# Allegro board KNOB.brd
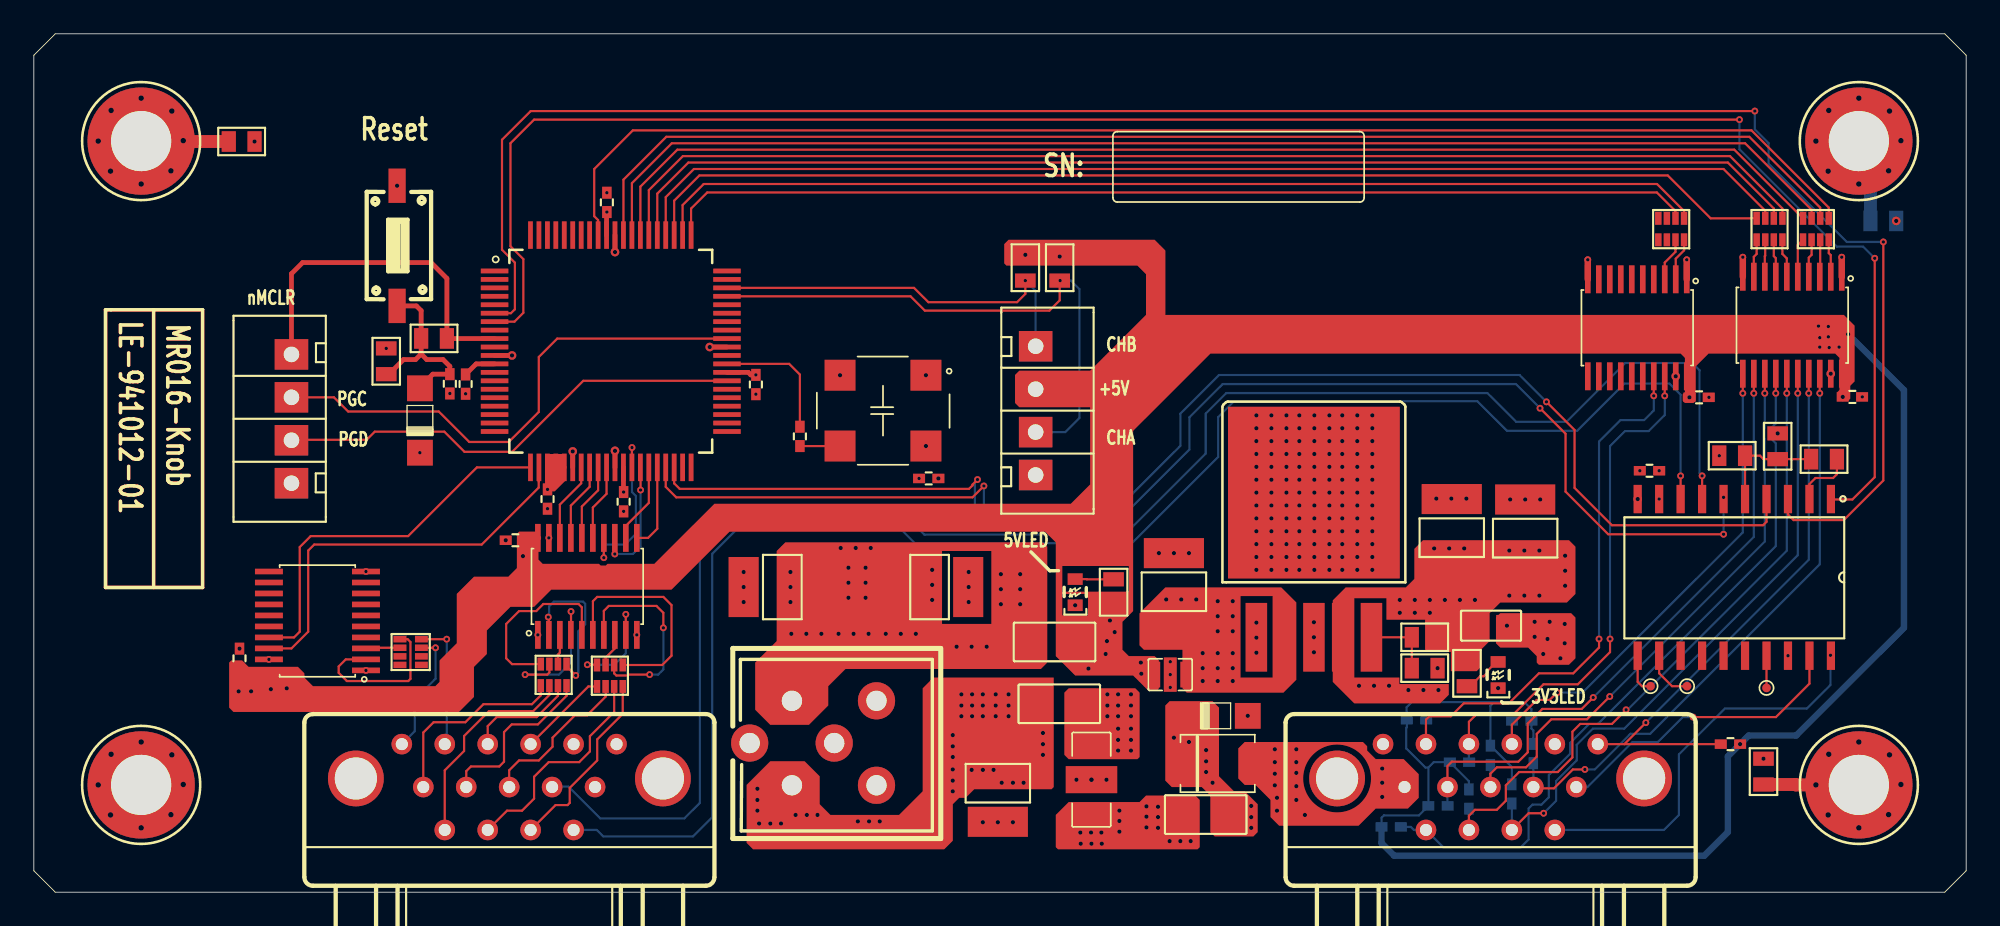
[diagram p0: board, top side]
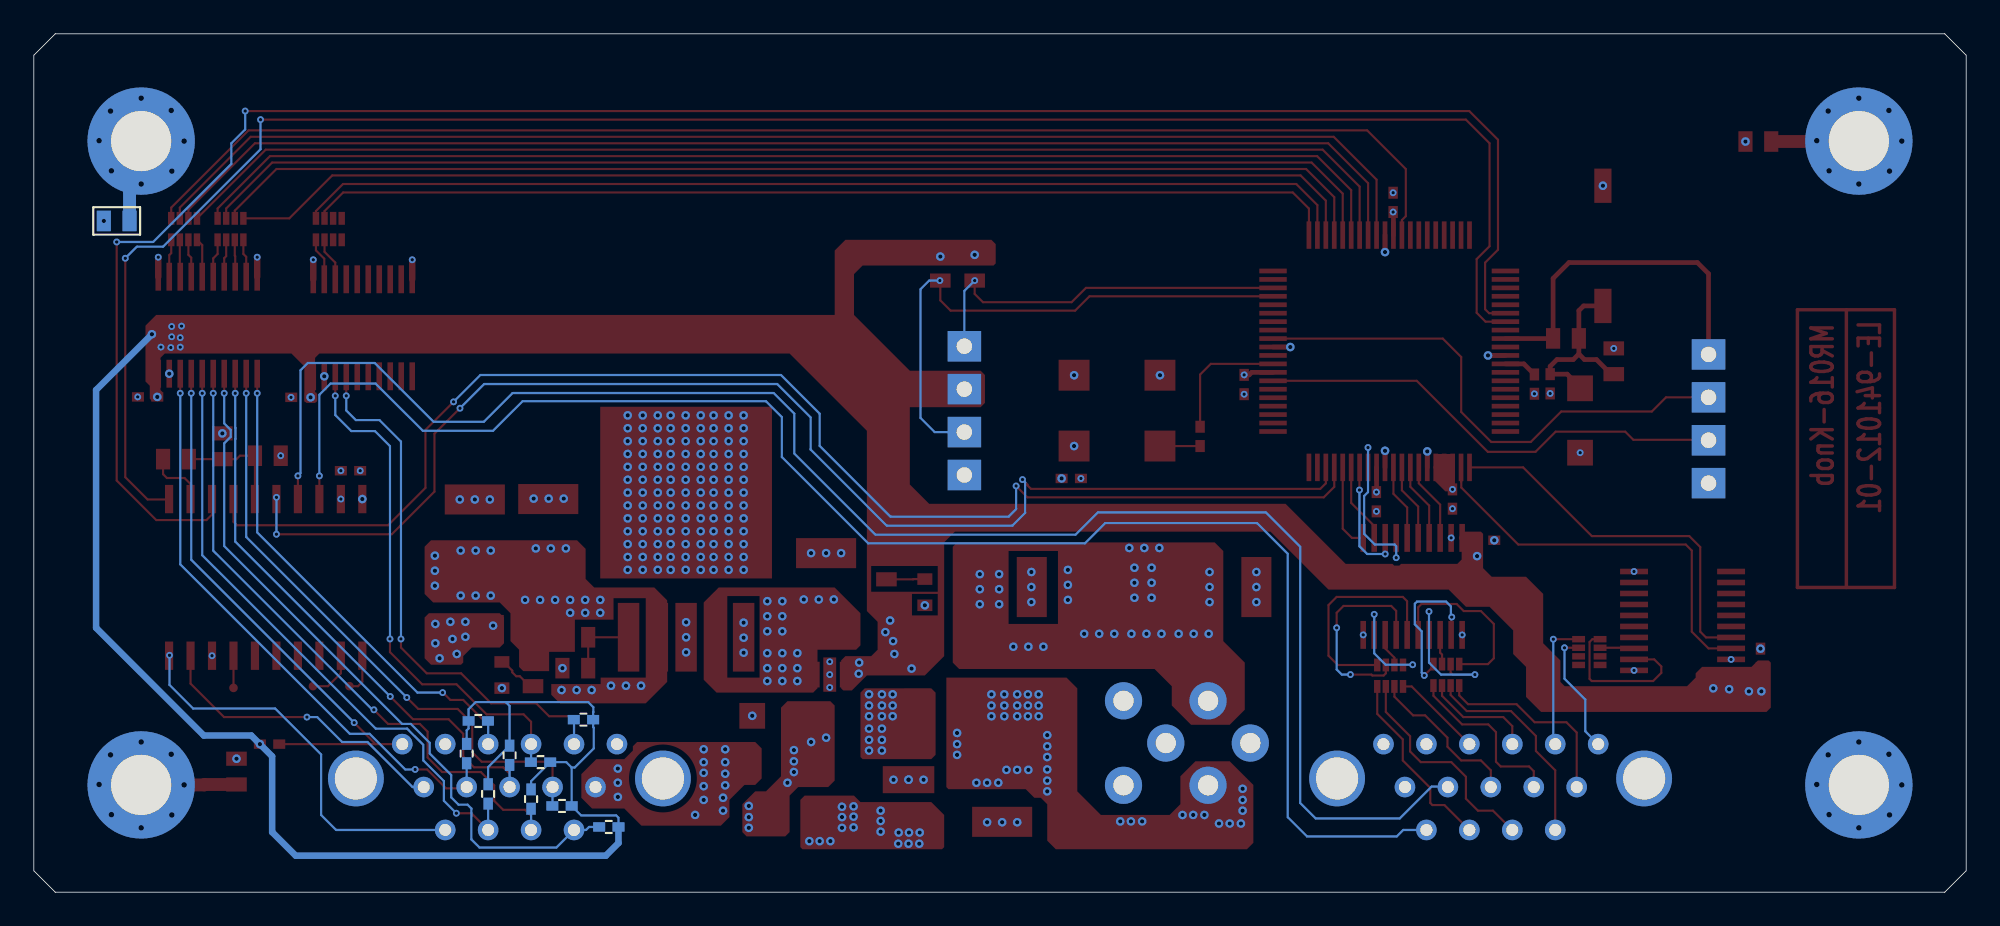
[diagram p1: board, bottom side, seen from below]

Outline 114.3 x 50.8 mm; copper layers: TOP, GND, VCC, BOTTOM. Coordinates in mm from the lower left corner of the outline.
Outline path: 0,49.53 1.27,50.8 113.03,50.8 114.3,49.53 114.3,1.27 113.03,0 1.27,0 0,1.27 0,49.53

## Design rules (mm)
net group N4518649: nets N4518649 N451853317
net group N4559206: nets N4545397 N4559206
net group NMCLR: nets N4540508 NMCLR
net group IO_SIG: nets LAT_LED0 LAT_LED1 LAT_LED2 LAT_LED3 LAT_LED4 LAT_LED5 LAT_LED6 LAT_LED7 LAT_LED8 LAT_LED9 PB0 PB1 PB2 PB3 PB4 PB5 PB6 PB7 PB8 PB9 RX232_DEBUG RX232_PC TX232_DEBUG TX232_PC
net group MECH_PINS: nets N4564556 N4564560 N4564564
net group PRG & ROTARY: nets ICHA ICHB PGC PGD

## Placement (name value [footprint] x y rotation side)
B1  NFM41PC  [FILT1806]  62.56 6.66 90 top
B2  BNX016-01  [BNX1]  42.34 8.83 0 top
B3  NFM21PC  [FILT0805]  67.22 12.88 0 top
C1  0.1uF  [0402]  30.39 23.27 270 top
C2  0.1uF  [0402]  34.89 23.11 270 top
C3  0.1uF  [0402]  33.9 40.82 90 top
C4  0.1uF  [0402]  42.71 30.04 270 top
C5  0.1uF  [0402]  25.54 30.07 270 top
C6  4.7uF  [0402]  24.61 30.09 270 top
C7  0.1uF  [0402]  52.93 24.49 180 top
C8  0.1uF  [0402]  95.57 24.94 180 top
C9  0.1uF  [0402]  28.49 20.83 180 top
C10  0.1uF  [0402]  12.17 13.84 90 top
C11  0.1uF  [0402]  107.57 29.31 0 top
C12  0.1uF  [0402]  98.5 29.29 0 top
C13  47uF  [1812]  57.02 6.45 270 top
C14  47uF  [1812]  44.27 18.06 180 top
C15  47uF  [1812]  52.98 18.06 0 top
C16  47uF  [1812]  67.44 17.78 90 top
C17  47uF  [1812]  83.87 20.98 90 top
C18  47uF  [1812]  88.21 20.95 90 top
C19  10nF 50V  [0603]  102.31 7.14 90 top
C20  10nF 50V  [0603]  109.4 39.73 0 bottom
C21  10nF 50V  [0603]  12.29 44.42 0 top
D1  D1N4148  [LL-34]  22.84 27.91 270 top
D2  PMEG5030  [SOD128]  70.02 7.62 180 top
D3  6V Zener  [LL-34]  69.9 10.44 180 top
D4  Blue LED  [LED0603]  61.59 17.75 270 top
D5  Blue LED  [LED0603]  86.61 12.85 270 top
F1  1A, Slow  [1206]  69.32 4.59 180 top
J1  Programming  [HDR4X1]  15.27 31.83 270 top
J2  ENS1J-B28-L00256L  [HDR4X1]  59.23 24.69 90 top
L1  BLM31PG  [1206]  60.66 11.15 180 top
NOREF  -  []  0 0 90 top
NOREF#2  -  []  6.35 6.35 90 top
NOREF#3  -  []  0 0 0 top
P1  IO CONN  [MIL-DB15]  28.12 6.22 180 top
P2  IO CONN  [MIL-DB15]  86.16 6.22 180 top
R1  10K  [0603]  20.85 31.42 90 top
R2  220  [0603]  23.67 32.77 0 top
R3  49.9 1%  [0402]  45.31 26.97 270 top
R4  NP/0  [0603]  105.89 25.63 0 top
R5  0  [0603]  100.46 25.83 0 top
R6  NP  [0603]  103.15 26.39 90 top
R7  NP/1K  [0603]  60.68 36.96 270 top
R8  NP/1K  [0603]  58.65 36.96 270 top
R9  0  [1206]  60.38 14.81 0 top
R10  680  [0603]  63.87 17.75 90 top
R11  NP/0  [0805]  86.19 15.77 180 top
R12  2K 1%  [0603]  82.27 15.09 0 top
R13  1.2K 1%  [0603]  82.27 13.26 180 top
R14  330  [0603]  84.77 12.95 270 top
R15  1K/2.2K  [0402]  80.29 3.86 180 bottom
R16  1K/2.2K  [0402]  81.79 10.21 180 bottom
R17  1K/2.2K  [0402]  83.06 5.11 180 bottom
R18  1K/2.2K  [0402]  84.33 7.7 180 bottom
R19  1K/2.2K  [0402]  84.89 5.51 90 bottom
R20  1K/2.2K  [0402]  86.16 8.1 90 bottom
R21  1K/2.2K  [0402]  87.43 5.82 90 bottom
R22  1K/2.2K  [0402]  88.01 10.13 0 bottom
R23  1K/2.2K  [0402]  88.7 8.2 90 bottom
R24  1K/2.2K  [0402]  100.36 8.76 0 top
RN1  150  [0402ARRAY]  31.51 13.5 180 top
RN2  150  [0402ARRAY]  34.84 13.45 180 top
RN3  150  [0402ARRAY]  21.66 14.97 270 top
RN4  150  [0402ARRAY]  106.17 39.88 180 top
RN5  150  [0402ARRAY]  103.43 39.88 180 top
RN6  150  [0402ARRAY]  97.61 39.88 180 top
S1  Screw  [HOLE-1]  6.35 6.35 0 top
S2  Screw  [HOLE-1]  107.95 6.35 0 top
S3  Screw  [HOLE-1]  107.95 44.45 0 top
S4  Screw  [HOLE-1]  6.35 44.45 0 top
SW1  uReset  [SMT-SW]  21.49 38.25 270 top
TP1  V+  [STP]  95.63 12.19 0 top
TP2  V+  [STP]  97.79 12.19 0 top
TP3  V-  [STP]  102.49 12.09 0 top
U1  14.7456MHz  [OSC]  50.23 28.5 270 top
U2  PIC18F87J50  [TQFP-80]  34.13 32.01 0 top
U3  MAX3233E  [SO-20]  100.58 18.63 270 top
U4  74HC245  [TSSOP20]  32.74 18.1 90 top
U5  74HC245  [TSSOP20]  16.78 16.05 180 top
U6  74HC245  [TSSOP20]  104.01 33.55 270 top
U7  74HC245  [TSSOP20]  94.84 33.4 270 top
U8  LT1764  [DDPACK]  75.72 15.11 0 top

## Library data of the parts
B1 = NFM18PS: room: PRI_FILT
B2 = BNX016: room: SEC_FILT
B3 = NFM18PS: room: 3V3Reg
C1-C5 = CAP NP: signal model: DEFAULT_CAPACITOR_100000pF_1_2; room: uicro
C6 = CAP NP: signal model: DEFAULT_CAPACITOR_4.7e+06pF_1_2; room: uicro
C7 = CAP NP: signal model: DEFAULT_CAPACITOR_100000pF_1_2; room: uOSC
C8 = CAP NP: signal model: DEFAULT_CAPACITOR_100000pF_1_2; room: RS232
C9 = CAP: signal model: DEFAULT_CAPACITOR_100000pF_1_2; room: oLAT1
C10 = CAP: signal model: DEFAULT_CAPACITOR_100000pF_1_2; room: OLAT2
C11 = CAP: signal model: DEFAULT_CAPACITOR_100000pF_1_2; room: iLAT1
C12 = CAP: signal model: DEFAULT_CAPACITOR_100000pF_1_2; room: iLAT2
C13 = CAP: signal model: DEFAULT_CAPACITOR_4.7e+07pF_1_2; room: PRI_FILT
C14 C15 = CAP: signal model: DEFAULT_CAPACITOR_4.7e+07pF_1_2; room: SEC_FILT
C16-C18 = CAP: signal model: DEFAULT_CAPACITOR_4.7e+07pF_1_2; room: 3V3Reg
C19-C21 = CAP: room: MECH
D1 = 1N4148: room: uicro
D2 = schottky: room: Protection
D3 = FLZ13VB: room: Protection
D4 = LED: room: PW_IN
D5 = LED: room: 3V3Reg
F1 = FUSE: room: Protection
J1 = 4 HEADER
J2 = HEADER 4: room: Rotary
L1 = INDUCTOR FERRITE/SM: signal model: DEFAULT_INDUCTOR_0.001nH_1_2; room: PRI_FILT
P1 = CONNECTOR DB15_1: room: IO CONs
P2 = CONNECTOR DB15_5: room: IO CONs
R1 = res: signal model: DEFAULT_RESISTOR_10000OHM_1_2; room: uicro
R2 = res: signal model: DEFAULT_RESISTOR_220.000000OHM_1_2; room: uicro
R3 = res: signal model: DEFAULT_RESISTOR_0.499OHM_1_2; room: uOSC
R4-R6 = res: signal model: DEFAULT_RESISTOR_0.001OHM_1_2; room: RS232
R7 R8 = res: signal model: DEFAULT_RESISTOR_0.001OHM_1_2; room: Rotary
R9 = res: signal model: DEFAULT_RESISTOR_0.001OHM_1_2; room: PW_IN
R10 = res: signal model: DEFAULT_RESISTOR_680.000000OHM_1_2; room: PW_IN
R11 = res: signal model: DEFAULT_RESISTOR_0.001OHM_1_2; room: 3V3Reg
R12 = res: signal model: DEFAULT_RESISTOR_20.000000OHM_1_2; room: 3V3Reg
R13 = res: signal model: DEFAULT_RESISTOR_12.000000OHM_1_2; room: 3V3Reg
R14 = res: signal model: DEFAULT_RESISTOR_330.000000OHM_1_2; room: 3V3Reg
R15-R24 = res: room: IO CONs
RN1 RN2 = RES Network: room: oLAT1
RN3 = RES Network: room: OLAT2
RN4 RN5 = RES Network: room: iLAT1
RN6 = RES Network: room: iLAT2
S1-S4 = Screw: room: MECH
SW1 = SW PUSHBUTTON: room: uicro
TP1-TP3 = TP: room: RS232
U1 = Oscillator: room: uOSC
U2 = PIC18F87J50: room: uicro
U3 = MAX3233E: room: RS232
U4 = 74HC245/SO: room: oLAT1
U5 = 74HC245/SO: room: OLAT2
U6 = 74HC245/SO: room: iLAT1
U7 = 74HC245/SO: room: iLAT2
U8 = LT1764: room: 3V3Reg

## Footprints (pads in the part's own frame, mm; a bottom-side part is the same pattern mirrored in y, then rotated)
0402
  rect 0.711x0.559 smd: 1(-0.572,0) 2(0.572,0)
0402ARRAY
  rect 0.381x0.762 smd: 1(0,0) 2(0.508,0) 3(1.016,0) 4(1.524,0) 5(1.524,1.27) 6(1.016,1.27) 7(0.508,1.27) 8(0,1.27)
0603
  rect 0.838x1.219 smd: 1(-0.762,0) 2(0.762,0)
0805
  rect 1.27x1.27 smd: 1(-0.94,0) 2(0.94,0)
1206
  rect 1.524x1.778 smd: 1(-1.397,0) 2(1.397,0)
1812
  rect 1.778x3.556 smd: 1(-2.286,0) 2(2.286,0)
BNX1
  round 2.2 hole 1.199: 1(2.499,-2.499) 2(2.499,2.499) 3(7.501,-2.499) 4(0,0) 5(4.999,0) 6(7.501,2.499)
DDPACK
  rect 1.27x4.064 smd: 1(-3.404,-0.025) 2(-1.702,-0.025) 3(0,-0.025) 4(1.702,-0.025) 5(3.404,-0.025)
  rect 10.16x10.16 smd: 6(0,8.534)
FILT0805
  rect 0.508x1.524 smd: 1(-0.851,0) 2(0.851,0)
  rect 0.762x2.032 smd: 3(0,0)
FILT1806
  rect 1.092x1.905 smd: 1(-2.052,0) 2(2.052,0)
  rect 1.6x3.048 smd: 3(0,0)
HDR4X1
  rect 1.803x1.981 hole 0.914: 1(0,-0.025) 2(2.54,-0.025) 3(5.08,-0.025) 4(7.62,-0.025)
HOLE-1
  round 6.35 hole 3.556: 1(0,0)
LED0603
  rect 0.686x0.889 smd: 1(-0.775,0) 2(0.775,0)
LL-34
  rect 1.524x1.524 smd: 1(-1.905,0) 2(1.905,0)
MIL-DB15
  round 1.219 hole 0.711: 1(-5.08,0) 2(-3.81,2.54) 3(-2.54,0) 4(-1.27,2.54) 5(1.27,2.54) 6(2.54,0) 7(3.81,2.54) 8(5.08,0) 9(-6.35,-2.54) 10(-3.81,-2.54) 11(-1.27,-2.54) 12(0,0) 13(1.27,-2.54) 14(3.81,-2.54) 15(6.35,-2.54)
  round 3.302 hole 2.489: 16(-9.093,-0.508) 17(9.068,-0.508)
OSC
  rect 1.829x1.829 smd: 1(-2.095,2.54) 2(-2.095,-2.54) 3(2.095,-2.54) 4(2.095,2.54)
SMT-SW
  rect 2.032x1.016 smd: 1(-3.556,0) 2(3.556,0)
SO-20
  rect 1.676x0.483 smd: 1(-4.636,5.715) 2(-4.636,4.445) 3(-4.636,3.175) 4(-4.636,1.905) 5(-4.636,0.635) 6(-4.636,-0.635) 7(-4.636,-1.905) 8(-4.636,-3.175) 9(-4.636,-4.445) 10(-4.636,-5.715) 11(4.636,-5.715) 12(4.636,-4.445) 13(4.636,-3.175) 14(4.636,-1.905) 15(4.636,-0.635) 16(4.636,0.635) 17(4.636,1.905) 18(4.636,3.175) 19(4.636,4.445) 20(4.636,5.715)
SOD128
  rect 1.199x1.9 smd: 1(-2.2,0) 2(2.2,0)
STP
  round 0.508 smd: 1(0,0)
TQFP-80
  rect 1.626x0.279 smd: 1(-6.873,4.75) 2(-6.873,4.249) 3(-6.873,3.749) 4(-6.873,3.251) 5(-6.873,2.751) 6(-6.873,2.25) 7(-6.873,1.75) 8(-6.873,1.25) 9(-6.873,0.749) 10(-6.873,0.249) 11(-6.873,-0.249) 12(-6.873,-0.749) 13(-6.873,-1.25) 14(-6.873,-1.75) 15(-6.873,-2.25) 16(-6.873,-2.751) 17(-6.873,-3.251) 18(-6.873,-3.749) 19(-6.873,-4.249) 20(-6.873,-4.75) 41(6.873,-4.75) 42(6.873,-4.249) 43(6.873,-3.749) 44(6.873,-3.251) 45(6.873,-2.751) 46(6.873,-2.25) 47(6.873,-1.75) 48(6.873,-1.25) 49(6.873,-0.749) 50(6.873,-0.249) 51(6.873,0.249) 52(6.873,0.749) 53(6.873,1.25) 54(6.873,1.75) 55(6.873,2.25) 56(6.873,2.751) 57(6.873,3.251) 58(6.873,3.749) 59(6.873,4.249) 60(6.873,4.75)
  rect 0.279x1.626 smd: 21(-4.75,-6.873) 22(-4.249,-6.873) 23(-3.749,-6.873) 24(-3.251,-6.873) 25(-2.751,-6.873) 26(-2.25,-6.873) 27(-1.75,-6.873) 28(-1.25,-6.873) 29(-0.749,-6.873) 30(-0.249,-6.873) 31(0.249,-6.873) 32(0.749,-6.873) 33(1.25,-6.873) 34(1.75,-6.873) 35(2.25,-6.873) 36(2.751,-6.873) 37(3.251,-6.873) 38(3.749,-6.873) 39(4.249,-6.873) 40(4.75,-6.873) 61(4.75,6.873) 62(4.249,6.873) 63(3.749,6.873) 64(3.251,6.873) 65(2.751,6.873) 66(2.25,6.873) 67(1.75,6.873) 68(1.25,6.873) 69(0.749,6.873) 70(0.249,6.873) 71(-0.249,6.873) 72(-0.749,6.873) 73(-1.25,6.873) 74(-1.75,6.873) 75(-2.25,6.873) 76(-2.751,6.873) 77(-3.251,6.873) 78(-3.749,6.873) 79(-4.249,6.873) 80(-4.75,6.873)
TSSOP20
  rect 1.651x0.33 smd: 1(-2.87,2.926) 2(-2.87,2.276) 3(-2.87,1.626) 4(-2.87,0.975) 5(-2.87,0.325) 6(-2.87,-0.325) 7(-2.87,-0.975) 8(-2.87,-1.626) 9(-2.87,-2.276) 10(-2.87,-2.926) 11(2.87,-2.926) 12(2.87,-2.276) 13(2.87,-1.626) 14(2.87,-0.975) 15(2.87,-0.325) 16(2.87,0.325) 17(2.87,0.975) 18(2.87,1.626) 19(2.87,2.276) 20(2.87,2.926)

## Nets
3V3: C1.1 C2.1 C3.1 C4.1 C7.1 C8.1 D1.2 R1.2 R5.1 R11.1 U1.1(EN/TRI) U1.4(VCC) U2.23(VUSB) U2.24(ENVREG) U2.25(AVDD) U2.32(VDD) U2.48(VDD_1) U2.71(VDD_2) U3.9(VCC) U3.10(F\O\R\C\E\O\F\F\)
5V: B3.1(IO1) C9.1 C10.1 C11.1 C12.1 J2.3 R7.1 R8.1 R9.2 R10.1 R15.2 R16.2 R17.2 R18.2 R19.2 R20.2 R21.2 R22.2 R23.2 R24.2 U4.20(VCC) U5.20(VCC) U6.20(VCC) U7.20(VCC)
5V_FILT: B2.2(CB) C14.1 C15.1 R9.1
5VI: B2.1(B) C13.1 L1.2
CGND: B1.3(G) B2.3(PSG) C13.2 D3.1(A) P2.15 P2.17(GND#17)
DG: B2.4(CG#4) B2.5(CG#5) B2.6(CG#6) B3.3(G) C1.2 C2.2 C3.2 C4.2 C5.2 C6.2 C7.2 C8.2 C9.2 C10.2 C11.2 C12.2 C14.2 C15.2 C16.2 C17.2 C18.2 C19.2 C20.2 C21.2 D4.2(CATHODE) D5.2(CATHODE) J1.4 J2.1 P1.1 P1.9 P1.10 P1.16(GND#16) P1.17(GND#17) P2.10 P2.16(GND#16) R6.2 R13.1 S1.1(H) SW1.1 U1.2(GND) U2.11(VSS) U2.26(AVSS) U2.31(VSS_1) U2.51(VSS_2) U2.70(VSS_3) U3.18(GND) U4.1(DIR) U4.10(GND) U4.19(O\E\) U5.1(DIR) U5.10(GND) U5.19(O\E\) U6.1(DIR) U6.10(GND) U6.19(O\E\) U7.1(DIR) U7.10(GND) U7.19(O\E\) U8.1(S\H\D\N\) U8.3(GND#3) U8.6(GND#6)
ICHA: J2.2 R7.2 U2.57(RB1/INT1/PMA4)
ICHB: J2.4 R8.2 U2.58(RB0/FLT0/INT0)
ILAT_PB0: RN4.1 U2.72(RD0/AD0/PMD0)
ILAT_PB1: RN4.2 U2.69(RD1/AD1/PMD1)
ILAT_PB2: RN4.3 U2.68(RD2/AD2/PMD2)
ILAT_PB3: RN4.4 U2.67(RD3/AD3/PMD3)
ILAT_PB4: RN5.1 U2.66(RD4/AD4/PMD4/SDO2)
ILAT_PB5: RN5.2 U2.65(RD5/AD5/PMD5/SDI2/SDA2)
ILAT_PB6: RN5.3 U2.64(RD6/AD6/PMD6/SCK2/SCL2)
ILAT_PB7: RN5.4 U2.63(RD7/AD7/PMD7/S\S\2\)
ILAT_PB8: RN6.1 U2.62(RJ0/ALE)
ILAT_PB9: RN6.2 U2.61(RJ1/O\E\)
IRX1: U2.38(RC7/RX1/DT1) U3.6(R1OUT)
IRX2: U2.7(RG2/PMA6/RX2/DT2) U3.1(R2OUT)
LAT_LED0: P1.6 RN1.8
LAT_LED1: P1.13 RN1.7
LAT_LED2: P1.7 RN1.6
LAT_LED3: P1.8 RN1.5
LAT_LED4: P1.4 RN2.8
LAT_LED5: P1.5 RN2.7
LAT_LED6: P1.12 RN2.6
LAT_LED7: P1.11 RN2.5
LAT_LED8: P1.14 RN3.8
LAT_LED9: P1.15 RN3.7
NMCLR: J1.1 R2.2 U2.9(\M\C\L\R\)
OLED0: U2.27(RA3/AN3/VREF+) U4.18(B0)
OLED1: U2.28(RA2/AN2/VREF-) U4.17(B1)
OLED2: U2.29(RA1/AN1) U4.16(B2)
OLED3: U2.30(RA0/AN0) U4.15(B3)
OLED4: U2.33(RA5/PMD4/AN4/C2INA) U4.14(B4)
OLED5: U2.34(RA4/PMD5/T0CKI) U4.13(B5)
OLED6: U2.35(RC1/T1OSI/ECCP2/P2A) U4.12(B6)
OLED7: U2.36(RC0/T1OSO/T13CKI) U4.11(B7)
OLED8: U2.22(RH4/PMD3/AN12/P3C/C2INC) U5.18(B0)
OLED9: U2.21(RH5/PMBE/AN13/P3B/C2IND) U5.17(B1)
OTX1: U2.37(RC6/TX1/CK1) U3.4(T1IN)
OTX2: U2.6(RG1/PMA7/TX2/CK2) U3.3(T2IN)
PB0: P2.3 R23.1 U6.18(B0)
PB1: P2.9 R24.1 U6.17(B1)
PB2: P2.4 R21.1 U6.16(B2)
PB3: P2.5 R19.1 U6.15(B3)
PB4: P2.7 R15.1 U6.14(B4)
PB5: P2.12 R20.1 U6.13(B5)
PB6: P2.6 R17.1 U6.12(B6)
PB7: P2.11 R22.1 U6.11(B7)
PB8: P2.13 R18.1 U7.18(B0)
PB9: P2.14 R16.1 U7.17(B1)
PGC: J1.2 U2.52(RB6/KBI2/PGC)
PGD: J1.3 U2.47(RB7/KBI3/PGD)
PRE3V: C17.1 C18.1 R11.2 R12.2 R14.1 U8.4(OUT)
PW_IN: D2.1(A) P2.8
PWI1: D2.2(K) D3.2(K) F1.1
PWI2: B1.1(IO1) F1.2
PWI3: B1.2(IO2) L1.1
REG_IN: B3.2(IO2) C16.1 U8.2(IN)
RX232_DEBUG: P2.1 U3.19(T2OUT)
RX232_PC: P1.3 U3.7(T1OUT)
TX232_DEBUG: P2.2 U3.20(R2IN)
TX232_PC: P1.2 U3.8(R1IN)
N4516923: R12.1 R13.2 U8.5(ADJ)
N4518449: TP1.1 U3.11(V +)
N4518453: TP2.1 U3.12(V+)
N4518457: TP3.1 U3.17(V-)
N4518649: R4.1 R5.2 R6.1 U3.5(FORCEON)
N4527797: RN4.8 U6.2(A0)
N4527803: RN5.7 U6.7(A5)
N4527809: RN4.7 U6.3(A1)
N4527815: RN5.5 U6.9(A7)
N4527821: RN4.5 U6.5(A3)
N4527827: RN5.8 U6.6(A4)
N4527833: RN5.6 U6.8(A6)
N4527839: RN4.6 U6.4(A2)
N4527957: RN6.7 U7.3(A1)
N4527963: RN6.8 U7.2(A0)
N4530864: D5.1(ANODE) R14.2
N4530991: D4.1(ANODE) R10.2
N4540508: C6.1 D1.1 R1.1 R2.1 SW1.2
N4541200: C5.1 U2.12(VDDCORE/VCAP)
N4545397: R3.2 U1.3(CKO)
N4559206: R3.1 U2.49(OSC1/CLKI/RA7)
N4562922: RN3.2 U5.3(A1)
N4562926: RN3.1 U5.2(A0)
N4563314: RN2.1 U4.6(A4)
N4563346: RN2.2 U4.7(A5)
N4563350: RN2.3 U4.8(A6)
N4563354: RN2.4 U4.9(A7)
N4563358: RN1.4 U4.5(A3)
N4563362: RN1.3 U4.4(A2)
N4563366: RN1.2 U4.3(A1)
N4563370: RN1.1 U4.2(A0)
N4564556: C21.1 S4.1(H)
N4564560: C20.1 S3.1(H)
N4564564: C19.1 S2.1(H)
N451853317: R4.2 U3.2(I\N\V\A\L\I\D\)

Pads without a net: RN3 3 4 5 6; RN6 3 4 5 6; U2 1 2 3 4 5 8 10 13 14 15 16 17 18 19 20 39 40 41 42 43 44 45 46 50 53 54 55 56 59 60 73 74 75 76 77 78 79 80; U3 13 14 15 16; U5 4 5 6 7 8 9 11 12 13 14 15 16; U7 4 5 6 7 8 9 11 12 13 14 15 16

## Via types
v1: diameter 0.406, hole 0.203, TOP to BOTTOM, 89 vias
v2: diameter 0.508, hole 0.254, TOP to BOTTOM, 372 vias
v3: diameter 0.61, hole 0.33, TOP to BOTTOM, 32 vias

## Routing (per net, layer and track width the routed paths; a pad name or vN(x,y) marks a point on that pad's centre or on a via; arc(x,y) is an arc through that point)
3V3: length 6.9
  TOP w0.279: U2.48 42.26,30.76 42.41,30.61 v1(42.71,30.61) ; U2.25 U2.24 U2.23 30.39,25.13 v1(30.39,23.84) ; v1(34.89,23.68) 34.88,23.69 U2.32 ; U2.71 33.88,40.23 v1(33.9,40.25)
  vias: v1(20.85,32.18) v1(22.83,26.01) v1(96.14,24.94) v1(96.14,23.27) v1(99.69,25.83) v2(52.77,30.59) v2(52.77,26.4) v2(53.51,24.49) v2(87.13,15.77) v2(88.77,16) v2(88.77,15.11) v2(89.28,14.1) v2(89.53,14.99) v2(89.66,16) v2(90.3,13.84) v2(90.55,15.88) v2(90.55,14.73) v2(94.87,23.27)
5V: length 88.8
  TOP w0.381: U4.20 29.67,20.83 C9.1
  BOTTOM w0.127: 86.39,11.25 81.51,11.25 81.2,10.95 81.2,10.67 81.22,10.66 R16.2 81.22,9.77 81.18,9.73 81.18,8.51 82.31,7.38 82.49,7.38 ; 86.39,11.25 86.16,11.02 R20.2 87.43,7.4 R21.2 ; 86.39,11.25 88.16,11.25 88.58,10.83 R22.2 88.58,9.69 88.7,9.58 R23.2 ; 82.49,7.38 R17.2 81.93,4.55 79.86,4.55 79.72,4.41 R15.2 ; 82.49,7.38 82.8,7.7 R18.2 84.89,6.57 R19.2
  BOTTOM w0.381: R15.2 79.72,2.91 80.47,2.16 98.81,2.16 100.2,3.56 100.2,8.04 v2(100.93,8.76) 101.43,9.27 104.24,9.27 110.62,15.65 110.62,29.72 v2(107.31,33.02)
  vias: v1(105.56,33.5) v1(105.64,32.82) v1(105.64,32.26) v1(106.15,33.48) v1(106.15,32.87) v1(106.2,32.23) v1(106.78,32.26) v2(12.12,11.89) v2(12.85,11.89) v2(14.02,12.01) v2(14.96,12.06) v2(28.93,19.89) v2(58.65,37.72) v2(60.68,37.62) v2(62.38,13.23) v2(63.4,14.1) v2(63.47,14.86) v2(63.65,16.08) v2(63.93,15.39) v2(65.48,13.59) v2(65.51,12.93) v2(97.93,29.29) v2(107,29.31)
5V_FILT:
  vias: v2(44.75,18.95) v2(44.75,18.06) v2(44.75,17.17) v2(44.81,15.29) v2(45.69,15.29) v2(46.58,15.29) v2(47.6,15.29) v2(47.73,20.37) v2(48.18,19.2) v2(48.18,18.31) v2(48.18,17.42) v2(48.49,15.29) v2(48.62,20.37) v2(49.2,19.2) v2(49.2,18.31) v2(49.2,17.42) v2(49.38,15.29) v2(49.5,20.37) v2(50.39,15.29) v2(51.28,15.29) v2(52.17,15.29) v2(53.14,19.08) v2(53.14,18.19) v2(53.14,17.3) v2(54.58,14.53) v2(55.47,14.53) v2(56.36,14.53) v2(57.2,18.82) v2(57.2,17.93) v2(57.2,17.04) v2(58.34,18.82) v2(58.34,17.93) v2(58.34,17.04)
5VI:
  vias: v2(42.8,6.12) v2(42.8,5.46) v2(42.8,4.83) v2(42.9,4.06) v2(43.56,4.06) v2(44.2,4.06) v2(45.06,4.57) v2(45.72,4.57) v2(46.35,4.57) v2(48.74,4.19) v2(49.41,4.19) v2(50.04,4.19) v2(54.36,9.3) v2(54.36,8.63) v2(54.36,8) v2(54.36,7.26) v2(54.36,6.6) v2(54.36,5.97) v2(54.86,11.71) v2(54.86,11.05) v2(54.86,10.41) v2(55.5,11.71) v2(55.5,11.05) v2(55.5,10.41) v2(55.47,7.24) v2(56.13,11.71) v2(56.13,11.05) v2(56.13,10.41) v2(56.14,7.24) v2(56.77,7.24) v2(56.9,11.71) v2(56.9,11.05) v2(56.9,10.41) v2(57.25,6.48) v2(57.66,11.71) v2(57.66,11.05) v2(57.66,10.41) v2(57.91,6.48) v2(58.55,6.48) v2(59.69,9.42) v2(59.69,8.76) v2(59.69,8.13)
CGND:
  vias: v2(56.13,4.14) v2(57.02,4.14) v2(57.91,4.14) v2(61.67,6.65) v2(62.56,6.66) v2(62.56,6.65) v2(63.45,6.65) v2(71.81,10.44)
DG: length 9.6
  TOP w0.279: U2.70 v2(34.38,37.88) ; U2.26 v2(31.88,26.09) ; U2.31 v2(34.38,26.12) ; U2.51 v2(39.98,32.26) ; U2.11 v2(28.29,31.77)
  TOP w0.381: U6.1 v1(106.94,37.58) ; U7.10 v1(91.92,37.43) ; U7.1 v1(97.77,37.43) ; U6.10 v1(101.09,37.58)
  vias: v1(13.91,13.78) v1(19.65,18.98) v1(19.65,13.13) v1(24.61,29.51) v1(25.54,29.5) v1(29.81,15.23) v1(30.39,22.69) v1(30.46,20.97) v1(33.9,41.39) v1(34.89,22.54) v1(35.67,15.23) v1(42.71,29.47) v1(52.36,24.49) v1(67.22,13.64) v1(67.22,12.88) v1(67.22,12.12) v1(95,24.94) v1(99.09,29.29) v1(103.76,14) v1(108.15,29.31) v2(12.17,14.41) v2(13.06,44.42) v2(21.49,41.81) v2(27.91,20.83) v2(41.99,18.95) v2(41.99,18.06) v2(41.99,17.17) v2(47.69,30.59) v2(55.3,18.95) v2(55.3,18.06) v2(55.3,17.17) v2(61.59,16.98) v2(66.55,20.07) v2(67.44,20.07) v2(68.33,20.07) v2(72.31,28.22) v2(72.31,27.46) v2(72.31,26.7) v2(72.31,25.93) v2(72.31,25.17) v2(72.31,24.41) v2(72.31,23.65) v2(72.31,22.89) v2(72.31,22.12) v2(72.31,21.36) v2(72.31,20.6) v2(72.31,19.84) v2(72.31,19.08) v2(72.31,15.95) v2(72.31,15.06) v2(72.31,14.17) v2(73.2,28.22) v2(73.2,27.46) v2(73.2,26.7) v2(73.2,25.93) v2(73.2,25.17) v2(73.2,24.41) v2(73.2,23.65) v2(73.2,22.89) v2(73.2,22.12) v2(73.2,21.36) v2(73.2,20.6) v2(73.2,19.84) v2(73.2,19.08) v2(74.09,28.22) v2(74.09,27.46) v2(74.09,26.7) v2(74.09,25.93) v2(74.09,25.17) v2(74.09,24.41) v2(74.09,23.65) v2(74.09,22.89) v2(74.09,22.12) v2(74.09,21.36) v2(74.09,20.6) v2(74.09,19.84) v2(74.09,19.08) v2(74.85,28.22) v2(74.85,27.46) v2(74.85,26.7) v2(74.85,25.93) v2(74.85,25.17) v2(74.85,24.41) v2(74.85,23.65) v2(74.85,22.89) v2(74.85,22.12) v2(74.85,21.36) v2(74.85,20.6) v2(74.85,19.84) v2(74.85,19.08) v2(75.74,28.22) v2(75.74,27.46) v2(75.74,26.7) v2(75.74,25.93) v2(75.74,25.17) v2(75.74,24.41) v2(75.74,23.65) v2(75.74,22.89) v2(75.74,22.12) v2(75.74,21.36) v2(75.74,20.6) v2(75.74,19.84) v2(75.74,19.08) v2(75.72,15.98) v2(75.72,15.09) v2(75.72,14.2) v2(76.63,28.22) v2(76.63,27.46) v2(76.63,26.7) v2(76.63,25.93) v2(76.63,25.17) v2(76.63,24.41) v2(76.63,23.65) v2(76.63,22.89) v2(76.63,22.12) v2(76.63,21.36) v2(76.63,20.6) v2(76.63,19.84) v2(76.63,19.08) v2(77.39,28.22) v2(77.39,27.46) v2(77.39,26.7) v2(77.39,25.93) v2(77.39,25.17) v2(77.39,24.41) v2(77.39,23.65) v2(77.39,22.89) v2(77.39,22.12) v2(77.39,21.36) v2(77.39,20.6) v2(77.39,19.84) v2(77.39,19.08) v2(78.28,28.22) v2(78.28,27.46) v2(78.28,26.7) v2(78.28,25.93) v2(78.28,25.17) v2(78.28,24.41) v2(78.28,23.65) v2(78.28,22.89) v2(78.28,22.12) v2(78.28,21.36) v2(78.28,20.6) v2(78.28,19.84) v2(78.28,19.08) v2(79.17,28.22) v2(79.17,27.46) v2(79.17,26.7) v2(79.17,25.93) v2(79.17,25.17) v2(79.17,24.41) v2(79.17,23.65) v2(79.17,22.89) v2(79.17,22.12) v2(79.17,21.36) v2(79.17,20.6) v2(79.17,19.84) v2(79.17,19.08) v2(82.96,23.29) v2(83.03,13.26) v2(83.85,23.29) v2(84.73,23.29) v2(86.61,12.08) v2(87.33,23.24) v2(88.21,23.24) v2(89.1,23.24) v2(97.12,30.53) v2(102.31,7.9) v2(103.15,27.15) v2(106.29,30.68) v2(110.16,39.73) v3(3.81,6.35) v3(4.54,4.57) v3(4.57,8.16) v3(6.35,8.89) v3(6.35,3.81) v3(8.11,4.59) v3(8.16,8.13) v3(8.84,6.38)
ICHA: length 33.4
  TOP w0.127: R7.2 60.68,35.03 60.07,34.42 52.7,34.42 51.86,35.27 U2.57
  BOTTOM w0.127: J2.2 61.01,27.23 61.85,28.07 61.85,35.69 61.34,36.2 v1(60.71,36.2)
ICHB: length 23.1
  TOP w0.127: U2.58 52.06,35.76 52.91,34.92 58.16,34.92 58.65,35.41 v1(58.65,36.2)
  BOTTOM w0.127: v1(58.65,36.2) 59.26,35.59 J2.4
ILAT_PB0: length 80.5
  TOP w0.127: U2.72 33.38,39.77 33.15,40.01 33.15,42.8 35.43,45.09 101.6,45.09 106.17,40.51 RN4.1
ILAT_PB1: length 77.5
  TOP w0.127: U2.69 34.88,42.17 37.41,44.7 101.47,44.7 105.66,40.51 RN4.2
ILAT_PB2: length 76
  TOP w0.127: U2.68 35.38,41.96 37.74,44.32 101.22,44.32 105.16,40.39 RN4.3
ILAT_PB3: length 74.2
  TOP w0.127: U2.67 35.88,41.76 38.06,43.94 100.58,43.94 RN4.4
ILAT_PB4: length 72.4
  TOP w0.127: RN5.1 103.43,40.46 100.33,43.56 38.39,43.56 36.38,41.55 U2.66
ILAT_PB5: length 71
  TOP w0.127: U2.65 36.88,41.34 38.72,43.18 100.2,43.18 102.92,40.46 RN5.2
ILAT_PB6: length 69.4
  TOP w0.127: U2.64 37.38,41.13 39.04,42.8 99.95,42.8 102.41,40.33 RN5.3
ILAT_PB7: length 67.7
  TOP w0.127: RN5.4 99.19,39.88 96.65,42.42 39.37,42.42 37.88,40.92 U2.63
ILAT_PB8: length 62.6
  TOP w0.127: RN6.1 97.61,40.31 96.01,41.91 39.62,41.91 38.38,40.66 U2.62
ILAT_PB9: length 61.1
  TOP w0.127: RN6.2 97.1,40.31 96,41.41 39.83,41.41 38.88,40.46 U2.61
IRX1: length 78.4
  TOP w0.127: v1(99.95,21.18) 93.12,21.18 90.6,23.71 90.6,27.13 v1(89.09,28.64) ; v1(55.82,24.42) 55.52,24.12 55.52,24.07 55.32,23.87 38.21,23.87 37.88,24.2 U2.38
  BOTTOM w0.127: v1(99.95,21.18) v1(99.95,23.37) ; v1(55.82,24.42) 55.66,24.26 55.66,22.45 56.42,21.69 63.85,21.69 68.35,26.2 68.35,28.1 70.32,30.07 87.66,30.07 v1(89.09,28.64)
IRX2: length 114.1
  TOP w0.127: v1(100.89,45.72) 29.59,45.72 28.19,44.32 28.19,38.23 28.96,37.47 28.96,34.29 28.43,33.76 U2.7 ; U3.1 106.32,23.24 107.57,23.24 108.89,24.56 v1(108.89,37.52)
  BOTTOM w0.127: v1(100.89,45.72) 100.89,43.97 106.65,38.2 108.2,38.2 v1(108.89,37.52)
LAT_LED0: length 10.4
  TOP w0.127: RN1.8 31.51,11.62 29.82,9.93 28.27,9.93 27.81,9.47 27.81,7.72 27.53,7.44 25.86,7.44 25.58,7.16 P1.6
LAT_LED1: length 6.6
  TOP w0.127: P1.13 26.85,9.83 27.38,10.36 29.74,10.36 31,11.62 RN1.7
LAT_LED2: length 12.6
  TOP w0.127: RN1.6 30.5,11.67 29.54,10.72 26.92,10.72 25.45,9.25 25.45,8.36 24.31,7.21 P1.7
LAT_LED3: length 11.7
  TOP w0.127: P1.8 23.04,9.45 23.65,10.06 25.53,10.06 26.59,11.13 29.46,11.13 29.99,11.65 RN1.5
LAT_LED4: length 11.2
  TOP w0.127: P1.4 30.86,5.16 31.57,5.16 31.7,5.28 31.7,6.17 33.32,7.8 33.32,9.04 34.84,10.55 RN2.8
LAT_LED5: length 13.2
  TOP w0.127: P1.5 27.99,4.83 28.88,4.83 29.59,5.54 29.59,6.83 30.45,7.7 32.26,7.7 32.89,8.33 32.89,9.23 34.33,10.67 RN2.7
LAT_LED6: length 9.4
  TOP w0.127: RN2.6 33.82,11.57 32.72,10.46 32,10.46 30.68,9.14 30.68,8.61 29.87,7.8 28.7,7.8 28.12,7.21 P1.12
LAT_LED7: length 5.3
  TOP w0.127: P1.11 32.8,12.18 RN2.5
LAT_LED8: length 7.8
  TOP w0.127: RN3.8 v1(24.42,14.97)
  BOTTOM w0.127: v1(24.42,14.97) 24.42,8.88 P1.14
LAT_LED9: length 7.4
  TOP w0.127: RN3.7 v1(23.76,14.47)
  BOTTOM w0.127: P1.15 22.53,9.53 22.53,11.4 23.76,12.64 v1(23.76,14.47)
NMCLR: length 21
  TOP w0.279: J1.1 15.24,36.6 15.9,37.26 23.5,37.26 24.43,36.32 R2.2 24.44,32.76 U2.9
OLED0: length 4.7
  TOP w0.127: U4.18 31.11,22.94 32.38,24.2 U2.27
OLED1: length 4.6
  TOP w0.127: U2.28 32.88,23.99 31.77,22.88 U4.17
OLED2: length 4.6
  TOP w0.127: U2.29 33.38,23.78 32.42,22.82 U4.16
OLED3: length 4.5
  TOP w0.127: U4.15 33.07,22.77 33.88,23.58 U2.30
OLED4: length 10.4
  TOP w0.127: U2.33 35.38,26.31 v1(35.38,26.31) ; U4.14 v1(33.72,19.8)
  BOTTOM w0.127: v1(33.72,19.8) 33.72,20.48 33.81,20.57 34.98,20.57 35.61,21.21 35.61,23.45 35.38,23.68 v1(35.38,26.31)
OLED5: length 7.3
  TOP w0.127: v1(35.89,23.8) 35.89,25.13 U2.34 ; U4.13 v1(34.37,20.02)
  BOTTOM w0.127: v1(34.37,20.02) 35.43,20.02 35.89,20.47 v1(35.89,23.8)
OLED6: length 4.7
  TOP w0.127: U4.12 35.02,21.68 36.38,23.04 U2.35
OLED7: length 5.1
  TOP w0.127: U2.36 36.88,21.51 36.33,20.97 U4.11
OLED8: length 23.9
  TOP w0.127: U5.18 15.24,14.43 16.23,15.42 16.23,20.22 16.59,20.57 26.49,20.57 29.87,23.95 29.87,24.29 29.88,24.31 U2.22
OLED9: length 22.6
  TOP w0.127: U2.21 26.21,25.14 22.14,21.07 16.38,21.07 15.73,20.43 15.73,15.42 15.39,15.08 U5.17
OTX1: length 80.1
  TOP w0.127: U2.37 37.38,23.99 38,23.37 55.52,23.37 v1(56.2,24.04) ; v1(89.47,29.02) 91.14,27.36 91.14,23.93 93.34,21.72 102.29,21.72 102.49,21.92 U3.4
  BOTTOM w0.127: v1(89.47,29.02) 87.88,30.61 70.1,30.61 67.82,28.32 67.82,26.42 63.63,22.23 56.64,22.23 56.2,22.67 v1(56.2,24.04)
OTX2: length 120.4
  TOP w0.127: U2.6 28.22,34.26 28.46,34.5 28.46,37.26 27.69,38.02 27.69,44.53 29.39,46.23 v1(101.8,46.23) ; U3.3 103.76,22.35 104.09,22.02 107.06,22.02 109.4,24.36 v1(109.4,38.48)
  BOTTOM w0.127: v1(109.4,38.48) 107.24,38.48 102.62,43.1 102.62,44.32 101.8,45.14 v1(101.8,46.23)
PB0: length 35.2
  TOP w0.127: P2.3 88.77,6.15 89.92,6.15 91.03,7.26 v1(91.74,7.26) ; U6.18 v1(105.64,29.53)
  BOTTOM w0.127: P2.3 R23.1 ; v1(91.74,7.26) 92.33,7.26 94.44,9.37 95.61,9.37 105.64,19.41 v1(105.64,29.53)
PB1: length 33.7
  TOP w0.127: U6.17 v1(104.99,29.53) ; 94.08,8.76 R24.1 ; 94.08,8.76 v1(95.35,10.03) ; 94.08,8.76 92.51,8.76
  BOTTOM w0.127: v1(95.35,10.03) 95.35,10.04 104.99,19.67 v1(104.99,29.53)
PB2: length 37.2
  TOP w0.127: U6.16 v1(104.34,29.53) ; P2.4 88.42,4.67 v1(89.31,4.67)
  BOTTOM w0.127: R21.1 P2.4 ; v1(104.34,29.53) 104.34,19.94 94.07,9.68 92.22,9.68 91.26,8.72 91.26,7.8 90.04,6.58 90.04,5.41 v1(89.31,4.67)
PB3: length 39.3
  TOP w0.127: P2.5 84.89,4.52 85.24,4.88 86.54,4.88 87.07,5.41 87.07,6.32 87.86,7.11 90.14,7.11 91.01,7.98 91.01,9.5 91.47,9.96 93.34,9.96 v1(94.18,10.79) ; U6.15 v1(103.69,29.53)
  BOTTOM w0.127: P2.5 R19.1 ; v1(103.69,29.53) 103.69,20.21 94.27,10.79 v1(94.18,10.79)
PB4: length 42.8
  TOP w0.127: U6.14 v1(103.04,29.53)
  BOTTOM w0.127: R15.1 81.46,3.86 81.64,3.68 P2.7 83.39,2.64 87.93,2.64 88.42,3.12 88.42,4.95 88.65,5.18 89.18,5.18 89.61,5.61 89.61,6.93 90.88,8.2 90.88,8.84 92,9.96 92.51,9.96 103.04,20.48 103.04,26.56 102.65,26.95 102.65,27.36 103.04,27.74 v1(103.04,29.53)
PB5: length 34.7
  TOP w0.127: U6.13 v1(102.39,29.53) ; P2.12 86.16,7.01 86.54,7.39 88.27,7.39 88.9,8.03 88.9,9.37 89.76,10.24 91.87,10.24 v1(93.22,11.58)
  BOTTOM w0.127: v1(102.39,29.53) 102.39,27.49 102.37,27.47 102.37,26.83 102.39,26.82 102.39,20.75 v1(93.22,11.58) ; P2.12 R20.1
PB6: length 36.8
  TOP w0.127: P2.6 83.62,7.47 83.87,7.72 87.81,7.72 88.37,8.28 88.37,9.98 89.23,10.85 91.56,10.85 v1(92.24,11.52) ; U6.12 v1(101.74,29.53)
  BOTTOM w0.127: v1(92.24,11.52) 101.74,21.02 v1(101.74,29.53) ; R17.1 83.62,5.12 P2.6
PB7: length 30.3
  TOP w0.127: P2.11 87.43,9.91 88.9,11.38 89.66,11.38 90.09,11.81 v1(90.12,11.81) ; U6.11 v1(101.09,29.53)
  BOTTOM w0.127: P2.11 87.43,10.12 R22.1 ; v1(90.12,11.81) 91.61,11.81 101.09,21.29 v1(101.09,29.53)
PB8: length 30.9
  TOP w0.127: P2.13 84.89,10.08 85.33,10.53 87.52,10.53 89.3,12.3 91.33,12.3 93.23,14.21 v1(93.23,14.99) ; U7.18 v1(96.47,29.38)
  BOTTOM w0.127: R18.1 84.89,7.71 P2.13 ; v1(93.23,14.99) 93.23,26.4 94.12,27.29 95.52,27.29 96.47,28.24 v1(96.47,29.38)
PB9: length 33.1
  TOP w0.127: U7.17 v1(95.82,29.38) ; P2.14 82.35,10.21 82.55,10.41 83.82,10.41 84.58,11.18 87.25,11.18 89.03,12.95 91.06,12.95 92.58,14.48 v1(92.58,14.99)
  BOTTOM w0.127: v1(92.58,14.99) 92.58,26.67 93.85,27.94 95.25,27.94 95.82,28.51 v1(95.82,29.38) ; P2.14 82.35,10.2 R16.1
PGC: length 31.3
  TOP w0.127: J1.2 17.75,29.29 18.59,28.45 23.95,28.45 25.76,26.64 28.09,26.64 29.87,28.42 29.87,31.67 30.96,32.76 U2.52
PGD: length 28.2
  TOP w0.127: J1.3 15.27,26.77 19.68,26.77 20.17,27.25 24.28,27.25 25.48,26.06 28.3,26.06 32.5,30.26 U2.47
PRE3V:
  vias: v2(78.38,12.22) v2(79.27,12.22) v2(80.16,12.22) v2(80.8,17.3) v2(80.8,16.54) v2(81.31,11.96) v2(81.69,17.3) v2(81.69,16.54) v2(82.19,11.96) v2(82.58,17.3) v2(82.58,16.54) v2(82.83,20.35) v2(83.08,11.96) v2(83.46,17.3) v2(83.72,20.35) v2(84.35,17.3) v2(84.61,20.35) v2(85.24,17.3) v2(87.27,20.22) v2(87.27,17.55) v2(88.16,20.22) v2(88.16,17.55) v2(89.05,20.22) v2(89.05,17.55) v2(90.58,19.91) v2(90.58,19.02) v2(90.58,18.14)
PW_IN:
  vias: v2(73.41,8.46) v2(73.41,7.7) v2(73.41,7.01) v2(73.41,6.32) v2(73.53,5.59) v2(73.53,4.83) v2(74.68,8.46) v2(74.68,7.7) v2(74.68,7.06) v2(74.68,6.27) v2(74.68,5.46) v2(75.18,4.57) v2(79.76,7.32) v2(79.76,6.48) v2(79.76,5.64)
PWI1:
  vias: v2(67.44,9.14) v2(68.33,8.89) v2(69.34,8.41) v2(69.34,7.74) v2(69.34,7.11) v2(69.72,6.48) v2(72.01,5.11) v2(72.01,4.44) v2(72.01,3.81)
PWI2:
  vias: v2(61.9,3.53) v2(61.93,2.87) v2(62.53,3.53) v2(62.56,2.87) v2(63.14,3.53) v2(63.17,2.87) v2(64.21,4.83) v2(64.21,4.22) v2(64.21,3.58) v2(65.81,5.08) v2(65.81,4.47) v2(65.81,3.84) v2(66.5,5.05) v2(66.5,4.45) v2(66.5,3.81) v2(67.18,3.02) v2(67.82,3.02) v2(68.43,3.02)
PWI3:
  vias: v2(63.5,11.71) v2(63.5,11.05) v2(63.5,10.41) v2(64.14,11.71) v2(64.14,11.05) v2(64.14,10.41) v2(64.14,9.68) v2(64.14,9.01) v2(64.14,8.38) v2(64.9,11.71) v2(64.9,11.05) v2(64.9,10.41) v2(64.9,9.68) v2(64.9,9.01) v2(64.9,8.38)
REG_IN:
  vias: v2(66.98,17.32) v2(67.87,17.32) v2(68.76,17.32) v2(69.14,14.15) v2(69.14,13.26) v2(69.14,12.5) v2(70.03,17.22) v2(70.03,16.33) v2(70.03,15.44) v2(70.03,14.15) v2(70.03,13.26) v2(70.03,12.5) v2(70.92,17.22) v2(70.92,16.33) v2(70.92,15.44) v2(70.92,14.15) v2(70.92,13.26) v2(70.92,12.5)
RX232_DEBUG: length 18
  TOP w0.127: v1(98.15,10.36) 103.05,10.36 105.03,12.34 U3.19
  BOTTOM w0.127: v1(98.15,10.36) 97.54,10.36 96.06,8.89 94.56,8.89 91.9,6.22 91.24,6.22
RX232_PC: length 100.5
  TOP w0.127: U3.7 v1(98.68,24.64)
  BOTTOM w0.127: v1(98.68,24.64) 98.53,24.79 98.53,30.89 98.09,31.32 94.13,31.32 90.65,27.84 87.68,27.84 85.98,29.54 70.54,29.54 69.32,28.32 69.32,25.96 64.52,21.16 52.68,21.16 51.36,22.48 41.43,22.48 39.4,20.45 39.4,5.28 38.48,4.37 33.5,4.37 31.62,6.25 30.68,6.25 P1.3
TX232_DEBUG: length 23.7
  BOTTOM w0.127: 89.97,3.68 96.42,3.68 97.31,4.57 97.31,8.15 100.03,10.87 104.88,10.87 106.27,12.27 v1(106.27,14.02)
TX232_PC: length 96.1
  TOP w0.127: U3.8 v1(97.41,24.64)
  BOTTOM w0.127: v1(97.41,24.64) 97.41,29.44 96.75,30.1 94.08,30.1 91.29,27.3 87.14,27.3 85.38,29.06 70.99,29.06 70.05,28.12 70.05,25.76 64.95,20.65 52.12,20.65 50.93,21.84 41.95,21.84 40.13,20.03 40.13,4.45 38.99,3.3 33.68,3.3 33.3,3.68 31.93,3.68
N4516923: length 4.2
  TOP w0.127: R13.2 R12.1 U8.5
N4518449: length 2.4
  TOP w0.127: U3.11 94.87,12.45 95.12,12.19 TP1.1
N4518453: length 3
  TOP w0.127: U3.12 96.14,12.95 96.9,12.19 TP2.1
N4518457: length 1.9
  TOP w0.127: TP3.1 U3.17
N4518649: length 6.6
  TOP w0.127: U3.5 R5.2 102.11,25.83 102.31,25.63 R6.1 R4.1
N4527797: length 2.2
  TOP w0.127: RN4.8 106.17,37.82 106.29,37.7 U6.2
N4527803: length 2.2
  TOP w0.127: RN5.7 102.92,37.64 103.04,37.53 U6.7
N4527809: length 2.2
  TOP w0.127: U6.3 105.66,36.45 RN4.7
N4527815: length 2.3
  TOP w0.127: U6.9 101.74,37.6 101.9,37.77 RN5.5
N4527821: length 2.3
  TOP w0.127: RN4.5 104.34,38.3 U6.5
N4527827: length 2.3
  TOP w0.127: U6.6 103.69,37.51 103.43,37.77 RN5.8
N4527833: length 2.2
  TOP w0.127: RN5.6 102.41,37.67 102.39,37.64 U6.8
N4527839: length 2.3
  TOP w0.127: U6.4 104.99,37.55 105.16,37.72 RN4.6
N4527957: length 2.6
  TOP w0.127: U7.3 96.47,37.26 97.1,37.9 RN6.7
N4527963: length 2.5
  TOP w0.127: RN6.8 97.61,37.98 97.12,37.49 U7.2
N4530864: length 2.5
  TOP w0.127: D5.1 86.51,13.63 86,13.11 86,13.01 85.77,12.78 85.55,12.78 84.96,12.19 R14.2
N4530991: length 2.3
  TOP w0.127: R10.2 62.29,18.52 62.28,18.53 D4.1
N4540508: length 11.3
  TOP w0.279: R1.1 21.01,30.66 21.87,31.52 22.58,31.52 22.91,31.85 ; D1.1 22.84,29.9 23.6,30.66 C6.1 24.61,31.12 24.21,31.52 23.24,31.52 22.91,31.85 ; SW1.2 22.63,34.7 22.91,34.42 R2.1 22.91,31.85
N4541200: length 2
  TOP w0.279: C5.1 26.16,31.26 U2.12
N4545397: length 2.4
  TOP w0.127: U1.3 R3.2
N4559206: length 7.7
  TOP w0.127: U2.49 41,31.27 44.68,31.27 45.31,30.63 R3.1
N4562922: length 2
  TOP w0.127: U5.3 19.68,14.47 RN3.2
N4562926: length 9.5
  TOP w0.127: RN3.1 22.11,14.97 22.28,14.81 22.28,12.63 22.15,12.5 18.52,12.5 18.03,12.98 18.03,13.36 18.45,13.78 U5.2
N4563314: length 13.1
  TOP w0.127: U4.6 33.07,15.23 33.07,17.22 33.32,17.48 37.24,17.48 37.72,16.99 37.72,14 37.17,13.45 RN2.1
N4563346: length 12.2
  TOP w0.127: U4.7 33.72,16.65 34.01,16.94 36.83,16.94 37.24,16.54 v1(37.24,15.65) ; v1(36.42,12.88) 35.18,12.88 35.13,12.82 34.46,12.82 34.33,12.95 RN2.2
  BOTTOM w0.127: v1(37.24,15.65) 37.24,13.18 36.93,12.88 v1(36.42,12.88)
N4563350: length 2
  TOP w0.127: U4.8 34.37,14.42 33.82,13.88 RN2.3
N4563354: length 6.7
  TOP w0.127: U4.9 v1(35.02,16.44) ; v1(32.74,13.46) 33.3,13.46 RN2.4
  BOTTOM w0.127: v1(32.74,13.46) 34.34,13.46 35.02,14.14 v1(35.02,16.44)
N4563358: length 10.9
  TOP w0.127: RN1.4 28.29,13.5 27.94,13.84 27.94,15.88 28.7,16.64 29.72,16.64 30.14,17.06 32.22,17.06 32.42,16.86 U4.5
N4563362: length 9.4
  TOP w0.127: RN1.3 30.5,13 30.37,12.88 v1(29.06,12.88) ; v1(31.78,16.61) 31.78,15.24 U4.4
  BOTTOM w0.127: v1(29.06,12.88) 31.06,12.88 31.78,13.59 v1(31.78,16.61)
N4563366: length 1.8
  TOP w0.127: U4.3 31.11,14.17 31,14.06 RN1.2
N4563370: length 9.4
  TOP w0.127: v1(30.43,16.28) 30.46,16.25 U4.2 ; v1(32.05,12.83) 31.51,13.37 RN1.1
  BOTTOM w0.127: v1(30.43,16.28) 30.48,16.33 30.48,16.92 30.76,17.2 32.49,17.2 32.61,17.07 32.61,15.85 32.21,15.44 32.21,12.98 v1(32.05,12.83)
N4564556: length 5.2
  TOP w0.762: C21.1 6.38,44.42 S4.1
  vias: v3(3.81,44.45) v3(4.54,42.67) v3(4.57,46.26) v3(6.35,46.99) v3(6.35,41.91) v3(8.11,42.69) v3(8.16,46.23) v3(8.84,44.48)
N4564560: length 5.2
  TOP w0.762: 107.92,47.02 v3(107.95,46.99)
  BOTTOM w0.762: S3.1 v3(107.95,41.91) 108.17,41.91 108.64,41.45 C20.1
  vias: v3(105.41,44.45) v3(106.14,42.67) v3(106.17,46.26) v3(109.71,42.69) v3(109.76,46.23) v3(110.44,44.48)
N4564564: length 5.6
  TOP w0.762: S2.1 v3(105.41,6.35) 104.22,6.35 104.19,6.38 C19.1
  vias: v3(106.14,4.57) v3(106.17,8.16) v3(107.95,8.89) v3(107.95,3.81) v3(109.71,4.59) v3(109.76,8.13) v3(110.44,6.38)
N451853317: length 3.6
  TOP w0.127: R4.2 106.65,24.74 106.43,24.51 105.38,24.51 105.03,24.16 U3.2

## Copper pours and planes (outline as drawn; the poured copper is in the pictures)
3V3 on TOP (solid shape): 31.45,24.36 30.81,23.72 30.25,23.72 30.25,25.93 31.45,25.93
3V3 on TOP (solid shape): 91.19,16.26 91.19,13.84 90.81,13.46 89.03,13.46 88.9,13.59 88.9,13.97 88.39,14.48 86.74,14.48 86.49,14.73 86.49,16.26 86.74,16.51 90.93,16.51
3V3 on VCC: 88.39,14.48 86.74,14.48 86.49,14.73 86.49,16.26 86.74,16.51 91.06,16.51 91.82,17.27 91.82,20.95 90.81,21.97 66.04,21.97 65.53,22.48 65.53,26.8 69.47,30.73 87.38,30.73 90.42,27.69 101.22,27.69 101.85,28.32 104.14,28.32 104.9,27.56 107.82,27.56 108.71,28.45 108.71,34.04 107.44,35.31 67.31,35.31 67.31,38.23 66.55,38.99 57.4,38.99 57.02,38.61 57.02,35.18 55.37,33.53 55.37,25.02 53.98,23.62 37.85,23.62 36.07,21.84 14.48,21.84 12.83,23.5 12.83,45.97 15.11,48.26 102.87,48.26 102.87,43.56 103.89,42.55 106.68,42.55 111.76,37.47 111.76,12.7 109.98,10.92 89.41,10.92 88.9,11.43 88.9,13.97
5V on TOP (solid shape): outline of 106 points within 11.56,10.67 107.7,38.61
5V on VCC: outline of 93 points within 11.56,10.67 107.7,38.61
5V_FILT on TOP (solid shape): 59.94,20.45 59.94,13.59 59.56,13.21 48.01,13.21 46.99,12.19 46.99,11.05 45.85,9.91 43.56,9.91 42.67,10.79 42.67,13.59 43.94,14.86 43.94,15.88 56.64,15.88 56.64,20.19 53.72,20.19 53.72,15.88 43.94,15.88 43.94,20.19 44.45,20.7 59.69,20.7
5V_FILT on VCC: 59.94,13.59 59.56,13.21 48.01,13.21 46.99,12.19 46.99,11.05 45.85,9.91 43.56,9.91 42.67,10.79 42.67,13.59 43.94,14.86 43.94,20.19 44.45,20.7 59.69,20.7 59.94,20.45
5VI on TOP (solid shape): 60.33,6.22 60.2,6.1 55.63,6.1 55.12,5.59 54.74,5.59 54.36,5.21 54.36,3.05 53.85,2.54 42.55,2.54 42.16,2.92 42.16,6.35 43.56,7.75 45.59,7.75 46.48,6.86 46.48,5.21 47.12,4.57 51.18,4.57 52.58,5.97 52.58,12.06 53.21,12.7 60.33,12.7
5VI on VCC: 60.33,12.7 60.33,6.22 60.2,6.1 55.63,6.1 55.12,5.59 54.74,5.59 54.36,5.21 54.36,3.05 53.85,2.54 42.55,2.54 42.16,2.92 42.16,6.35 43.56,7.75 45.59,7.75 46.48,6.86 46.48,5.21 47.12,4.57 51.18,4.57 52.58,5.97 52.58,12.06 53.21,12.7
CGND on GND: 78.61,2.54 78.61,4.09 79.48,4.95 79.48,7.24 79.86,7.62 80.54,7.62 81.08,8.15 81.08,9.35 80.44,9.98 74.63,9.98 73,11.61 70.31,11.61 70,11.3 70,7.14 69.34,6.48 66.22,6.48 64.85,7.85 49.12,7.85 47.88,6.6 47.88,2.54
DG on GND: 104.14,3.05 2.54,3.05 2.54,48.26 111.25,48.26 111.25,10.16 106.43,10.16 104.14,7.87
PRE3V on TOP (solid shape): 91.19,20.45 91.19,17.65 90.68,17.14 86.74,17.14 86.11,16.51 86.11,14.86 85.6,14.35 85.6,13.34 85.34,13.08 83.82,13.08 83.82,14.22 82.3,14.22 82.3,16.13 80.01,16.13 80.01,17.4 78.11,17.4 78.11,12.7 80.77,12.7 80.77,12.32 83.69,12.32 83.69,11.68 83.19,11.18 78.11,11.18 76.83,12.45 76.83,17.27 77.6,18.03 81.15,18.03 81.66,18.54 81.66,20.32 82.17,20.83 90.81,20.83
PRE3V on VCC: 83.19,11.81 77.6,11.81 76.83,12.57 76.83,17.27 77.47,17.91 81.03,17.91 81.66,18.54 81.66,20.32 82.17,20.83 90.81,20.83 91.19,20.45 91.19,17.65 90.68,17.14 86.74,17.14 86.11,16.51 86.11,14.86 85.6,14.35 85.6,13.34 85.34,13.08 84.07,13.08 83.69,12.7 83.69,12.32
PW_IN on TOP (solid shape): outline of 121 points within 71.25,3.94 81.92,8.89
PW_IN on VCC: 81.92,6.99 81.92,5.59 81.28,4.95 79.25,4.95 78.61,4.32 78.61,3.43 73.41,3.43 73.15,3.68 73.15,5.46 72.26,6.35 71.63,6.35 71.25,6.73 71.25,8.51 71.88,9.14 79.76,9.14
PWI1 on TOP (solid shape): 70.1,10.92 70.1,6.86 70.99,5.97 71.63,5.97 72.39,5.21 72.39,3.56 72.14,3.3 69.85,3.3 69.6,3.56 69.6,5.71 69.09,6.22 67.31,6.22 66.93,6.6 66.93,11.05 67.18,11.3 69.72,11.3
PWI1 on VCC: 72.14,3.3 69.85,3.3 69.6,3.56 69.6,5.71 69.09,6.22 67.31,6.22 66.93,6.6 66.93,11.05 67.18,11.3 69.72,11.3 70.1,10.92 70.1,6.86 70.99,5.97 71.63,5.97 72.39,5.21 72.39,3.56
PWI2 on TOP (solid shape): 68.96,5.46 68.96,2.67 68.83,2.54 60.58,2.54 60.45,2.67 60.45,4.57 61.21,5.33 65.41,5.33 65.79,5.71 68.71,5.71
PWI2 on VCC: 68.96,5.46 68.96,2.67 68.83,2.54 60.58,2.54 60.45,2.67 60.45,4.57 61.21,5.33 65.41,5.33 65.79,5.71 68.71,5.71
PWI3 on TOP (solid shape): 65.41,11.81 65.41,8 65.28,7.87 61.21,7.87 60.96,8.13 60.96,11.81 61.21,12.06 65.15,12.06
PWI3 on VCC: 61.09,7.87 60.96,8 60.96,11.81 61.21,12.06 65.15,12.06 65.41,11.81 65.41,8 65.28,7.87
REG_IN on TOP (solid shape): 74.68,17.14 74.68,12.57 73.91,11.81 68.2,11.81 67.94,12.06 67.94,12.7 73.28,12.7 73.28,17.53 71.37,17.53 71.37,12.7 67.94,12.7 67.94,14.35 65.66,14.35 65.41,14.61 65.41,16.51 66.93,18.03 73.79,18.03
REG_IN on VCC: 74.17,12.06 67.94,12.06 67.94,14.35 65.66,14.35 65.41,14.61 65.41,16.51 66.8,17.91 73.91,17.91 74.68,17.14 74.68,12.57

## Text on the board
TOP: LE-941012-01 | MR016-Knob
Ref Des/Silkscreen Top: nMCLR | PGC | PGD | 5VLED | +5V | CHB | CHA | 3V3LED | Reset | SN: | LE-941012-01 | MR016-Knob
